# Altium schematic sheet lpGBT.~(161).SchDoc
size C
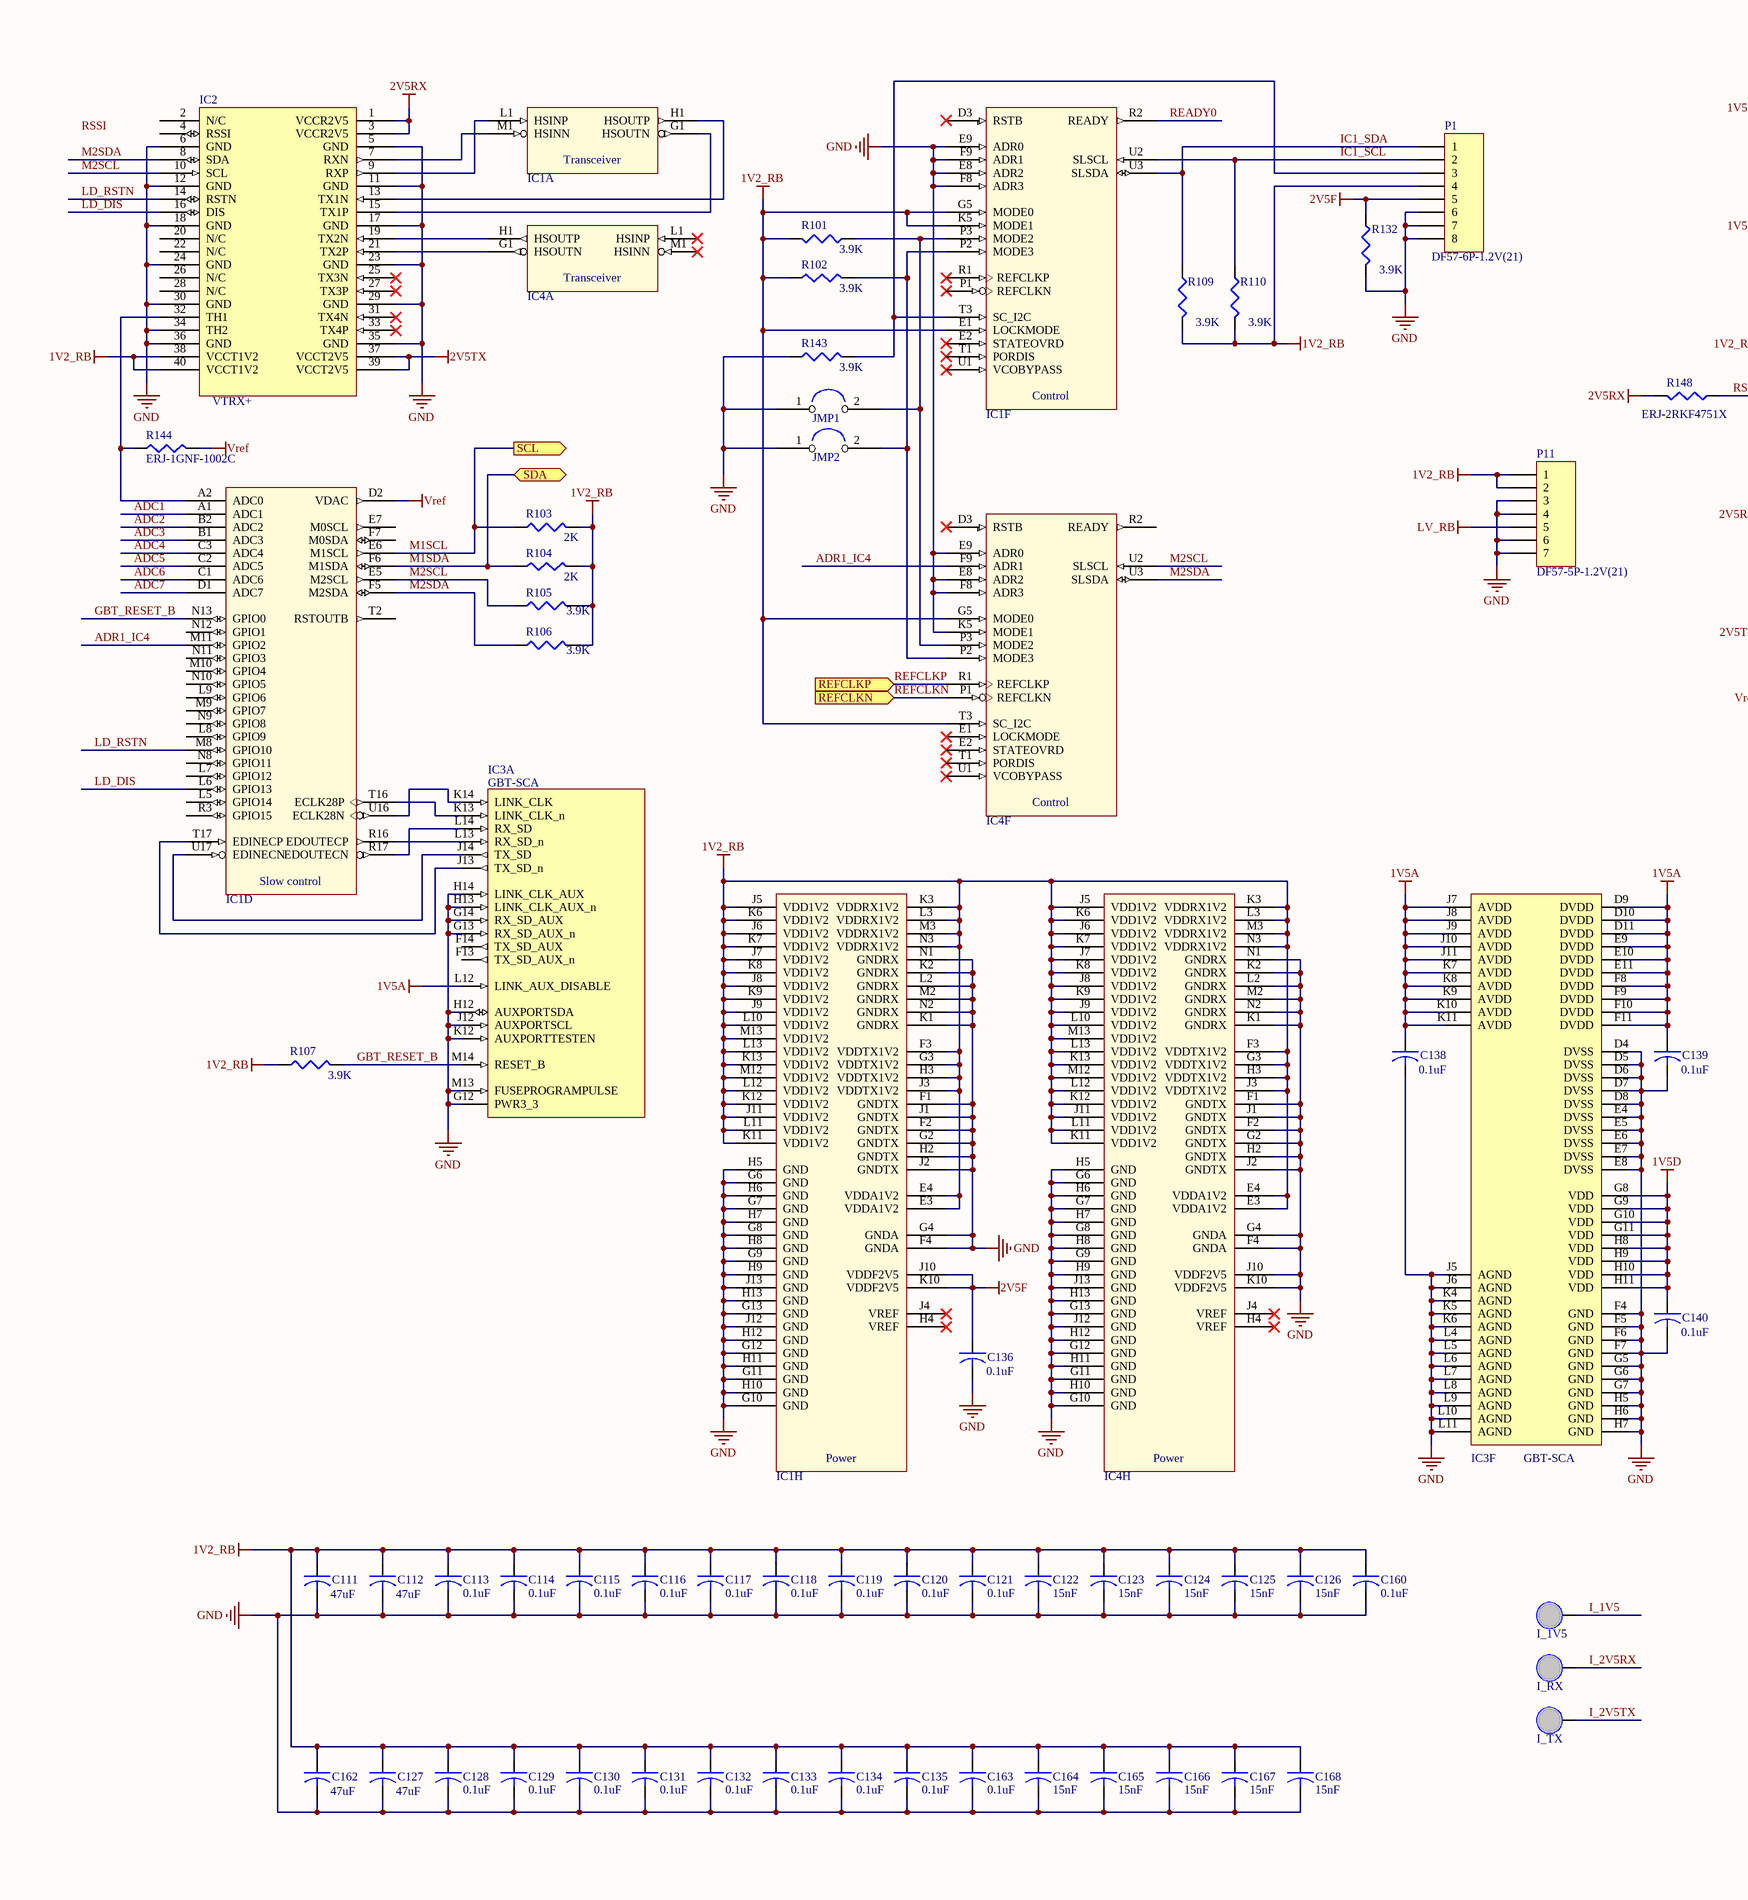
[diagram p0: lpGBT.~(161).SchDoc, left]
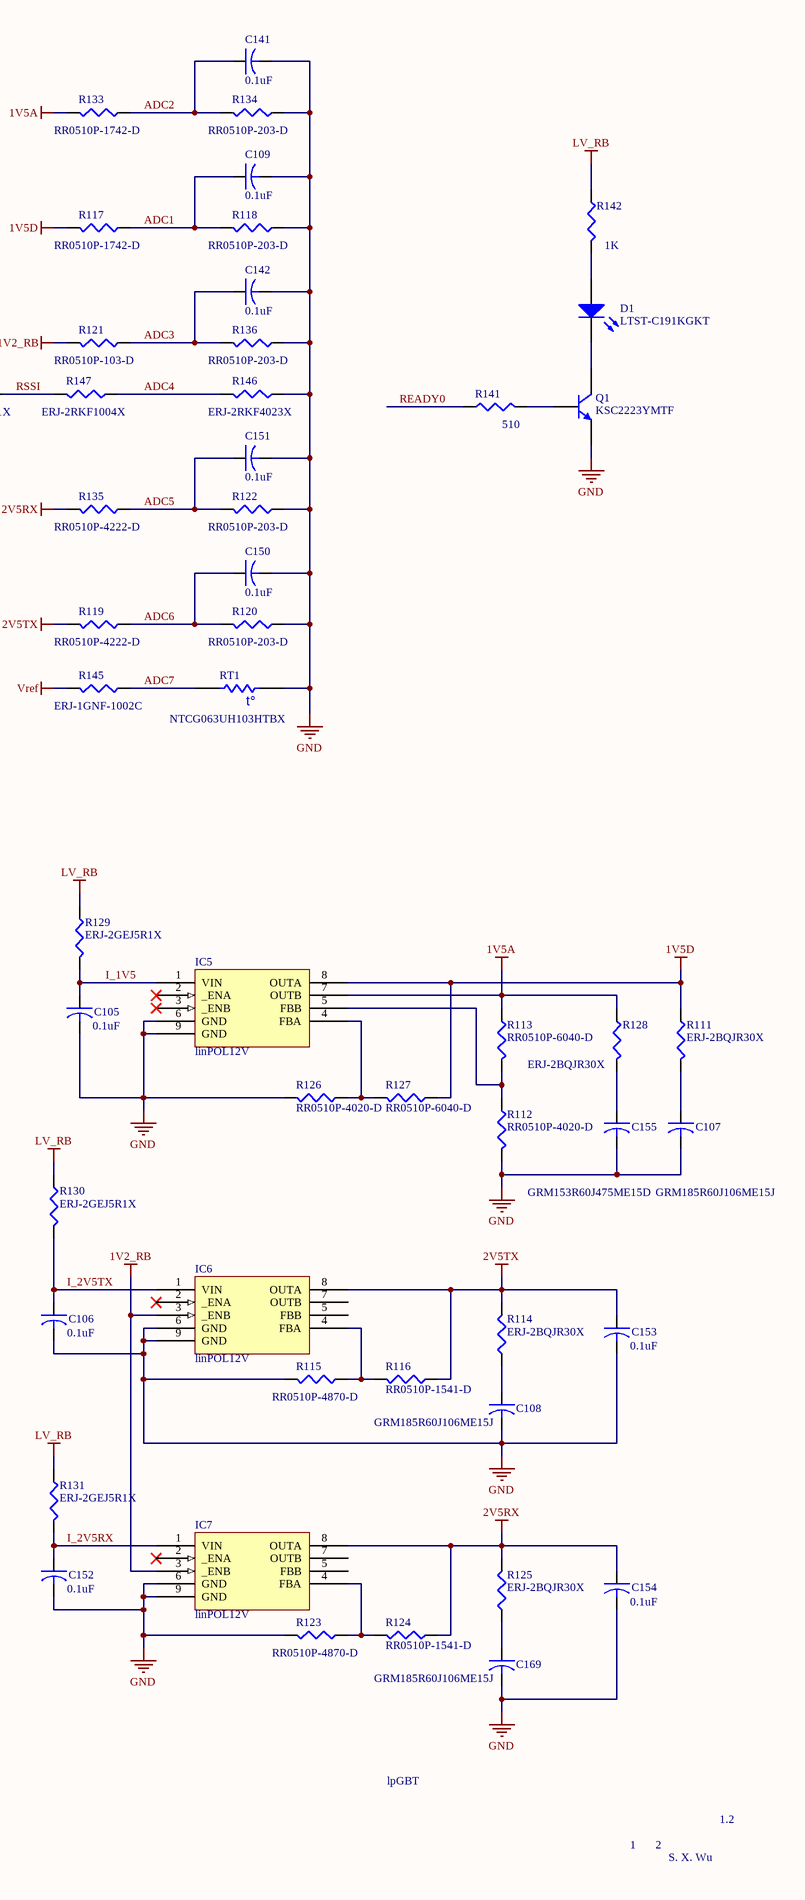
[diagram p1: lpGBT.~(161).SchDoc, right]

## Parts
C105  value 0.1uF  [capc1005n]  (hidden comment: GRM155R71E104ME14D)
C106  value 0.1uF  [capc1005n]  (hidden comment: GRM155R71E104ME14D)
C107  GRM185R60J106ME15J  [CAPC1608N]
C108  GRM185R60J106ME15J  [CAPC1608N]
C109  value 0.1uF  [capc1005n]  (hidden comment: GRM155R71E104ME14D)
C111  value 47uF  [capc2012n]  (hidden comment: GRM188R60J476ME15D)
C112  value 47uF  [capc2012n]  (hidden comment: GRM188R60J476ME15D)
C113  value 0.1uF  [capc0603n]  (hidden comment: GRM033R61C6104KE84D)
C114  value 0.1uF  [capc0603n]  (hidden comment: GRM033R61C6104KE84D)
C115  value 0.1uF  [capc0603n]  (hidden comment: GRM033R61C6104KE84D)
C116  value 0.1uF  [capc0603n]  (hidden comment: GRM033R61C6104KE84D)
C117  value 0.1uF  [capc0603n]  (hidden comment: GRM033R61C6104KE84D)
C118  value 0.1uF  [capc0603n]  (hidden comment: GRM033R61C6104KE84D)
C119  value 0.1uF  [capc0603n]  (hidden comment: GRM033R61C6104KE84D)
C120  value 0.1uF  [capc0603n]  (hidden comment: GRM033R61C6104KE84D)
C121  value 0.1uF  [capc0603n]  (hidden comment: GRM033R61C6104KE84D)
C122  value 15nF  [capc0603n]  (hidden comment: GRM033R61C153KE84D)
C123  value 15nF  [capc0603n]  (hidden comment: GRM033R61C153KE84D)
C124  value 15nF  [capc0603n]  (hidden comment: GRM033R61C153KE84D)
C125  value 15nF  [capc0603n]  (hidden comment: GRM033R61C153KE84D)
C126  value 15nF  [capc0603n]  (hidden comment: GRM033R61C153KE84D)
C127  value 47uF  [capc2012n]  (hidden comment: GRM188R60J476ME15D)
C128  value 0.1uF  [capc0603n]  (hidden comment: GRM033R61C6104KE84D)
C129  value 0.1uF  [capc0603n]  (hidden comment: GRM033R61C6104KE84D)
C130  value 0.1uF  [capc0603n]  (hidden comment: GRM033R61C6104KE84D)
C131  value 0.1uF  [capc0603n]  (hidden comment: GRM033R61C6104KE84D)
C132  value 0.1uF  [capc0603n]  (hidden comment: GRM033R61C6104KE84D)
C133  value 0.1uF  [capc0603n]  (hidden comment: GRM033R61C6104KE84D)
C134  value 0.1uF  [capc0603n]  (hidden comment: GRM033R61C6104KE84D)
C135  value 0.1uF  [capc0603n]  (hidden comment: GRM033R61C6104KE84D)
C136  value 0.1uF  [capc0603n]  (hidden comment: GRM033R61C6104KE84D)
C138  value 0.1uF  [capc1005n]  (hidden comment: GRM155R71E104ME14D)
C139  value 0.1uF  [capc1005n]  (hidden comment: GRM155R71E104ME14D)
C140  value 0.1uF  [capc1005n]  (hidden comment: GRM155R71E104ME14D)
C141  value 0.1uF  [capc1005n]  (hidden comment: GRM155R71E104ME14D)
C142  value 0.1uF  [capc1005n]  (hidden comment: GRM155R71E104ME14D)
C150  value 0.1uF  [capc1005n]  (hidden comment: GRM155R71E104ME14D)
C151  value 0.1uF  [capc1005n]  (hidden comment: GRM155R71E104ME14D)
C152  value 0.1uF  [capc1005n]  (hidden comment: GRM155R71E104ME14D)
C153  value 0.1uF  [capc1005n]  (hidden comment: GRM155R71E104ME14D)
C154  value 0.1uF  [capc1005n]  (hidden comment: GRM155R71E104ME14D)
C155  GRM153R60J475ME15D  [capc1005n]
C160  value 0.1uF  [capc1005n]  (hidden comment: GRM155R71E104ME14D)
C162  value 47uF  [capc2012n]  (hidden comment: GRM188R60J476ME15D)
C163  value 0.1uF  [capc0603n]  (hidden comment: GRM033R61C6104KE84D)
C164  value 15nF  [capc0603n]  (hidden comment: GRM033R61C153KE84D)
C165  value 15nF  [capc0603n]  (hidden comment: GRM033R61C153KE84D)
C166  value 15nF  [capc0603n]  (hidden comment: GRM033R61C153KE84D)
C167  value 15nF  [capc0603n]  (hidden comment: GRM033R61C153KE84D)
C168  value 15nF  [capc0603n]  (hidden comment: GRM033R61C153KE84D)
C169  GRM185R60J106ME15J  [CAPC1608N]
D1  LTST-C191KGKT  [LED_RED]
IC1  LPGBT  [BGA289X17]  (value not drawn)  (parts A,D,F,H of 8)
IC2  DF40C-40DS-0.4V  [vtrx+]  (value not drawn)
IC3  GBT-SCA  [BGA196C80P14X14_1200X1200X170]  (parts A,F of 6)
IC4  LPGBT  [BGA289X17]  (value not drawn)  (parts A,F,H of 8)
IC5  linPOL12V  [WDFNX208]
IC6  linPOL12V  [WDFNX208]
IC7  linPOL12V  [WDFNX208]
JMP1  Not a component, printed on PCB  [JMP2PCB]  (value not drawn)  (no BOM)
JMP2  Not a component, printed on PCB  [JMP2PCB]  (value not drawn)  (no BOM)
P1  DF57-6P-1.2V(21)  [df57-6]
P11  DF57-5P-1.2V(21)  [DF57-5]
Q1  KSC2223YMTF  [SOT-23]
R101  Parameter 1: 3.9K  [resc1005n]  (hidden comment: ERJ-2GEJ392X)
R102  Parameter 1: 3.9K  [resc1005n]  (hidden comment: ERJ-2GEJ392X)
R103  Parameter 1: 2K  [resc1005n]  (hidden comment: ERJ-2GEJ202X)
R104  Parameter 1: 2K  [resc1005n]  (hidden comment: ERJ-2GEJ202X)
R105  Parameter 1: 3.9K  [resc1005n]  (hidden comment: ERJ-2GEJ392X)
R106  Parameter 1: 3.9K  [resc1005n]  (hidden comment: ERJ-2GEJ392X)
R107  Parameter 1: 3.9K  [resc1005n]  (hidden comment: ERJ-2GEJ392X)
R109  Parameter 1: 3.9K  [resc1005n]  (hidden comment: ERJ-2GEJ392X)
R110  Parameter 1: 3.9K  [resc1005n]  (hidden comment: ERJ-2GEJ392X)
R111  ERJ-2BQJR30X  [resc1005n]
R112  RR0510P-4020-D  [resc1005n]
R113  RR0510P-6040-D  [resc1005n]
R114  ERJ-2BQJR30X  [resc1005n]
R115  RR0510P-4870-D  [resc1005n]
R116  RR0510P-1541-D  [resc1005n]
R117  RR0510P-1742-D  [resc1005n]
R118  RR0510P-203-D  [resc1005n]
R119  RR0510P-4222-D  [resc1005n]
R120  RR0510P-203-D  [resc1005n]
R121  RR0510P-103-D  [resc1005n]
R122  RR0510P-203-D  [resc1005n]
R123  RR0510P-4870-D  [resc1005n]
R124  RR0510P-1541-D  [resc1005n]
R125  ERJ-2BQJR30X  [resc1005n]
R126  RR0510P-4020-D  [resc1005n]
R127  RR0510P-6040-D  [resc1005n]
R128  ERJ-2BQJR30X  [resc1005n]
R129  ERJ-2GEJ5R1X  [resc1005n]
R130  ERJ-2GEJ5R1X  [resc1005n]
R131  ERJ-2GEJ5R1X  [resc1005n]
R132  Parameter 1: 3.9K  [resc1005n]  (hidden comment: ERJ-2GEJ392X)
R133  RR0510P-1742-D  [resc1005n]
R134  RR0510P-203-D  [resc1005n]
R135  RR0510P-4222-D  [resc1005n]
R136  RR0510P-203-D  [resc1005n]
R141  Parameter 1: 510  [resc1005n]  (hidden comment: ERJ-2GEJ511X)
R142  Parameter 1: 1K  [resc1005n]  (hidden comment: ERJ-2GEJ102X)
R143  Parameter 1: 3.9K  [resc1005n]  (hidden comment: ERJ-2GEJ392X)
R144  ERJ-1GNF-1002C  [resc0603]
R145  ERJ-1GNF-1002C  [resc0603]
R146  ERJ-2RKF4023X  [resc1005n]
R147  ERJ-2RKF1004X  [resc1005n]
R148  ERJ-2RKF4751X  [resc1005n]
RT1  NTCG063UH103HTBX  [resc0603]
TP15  I_1V5  [testpoint]  (no BOM)
TP16  I_RX  [testpoint]  (no BOM)
TP17  I_TX  [testpoint]  (no BOM)

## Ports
REFCLKN (in), REFCLKP (in), SCL (out), SDA (bidir)

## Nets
1V2_RB: C111.1 C112.1 C113.1 C114.1 C115.1 C116.1 C117.1 C118.1 C119.1 C120.1 C121.1 C122.1 C123.1 C124.1 C125.1 C126.1 C127.1 C128.1 C129.1 C130.1 C131.1 C132.1 C133.1 C134.1 C135.1 C160.1 C162.1 C163.1 C164.1 C165.1 C166.1 C167.1 C168.1 IC1.E1(LOCKMODE) IC1.E3(VDDA1V2) IC1.E4(VDDA1V2) IC1.F3(VDDTX1V2) IC1.G3(VDDTX1V2) IC1.G5(MODE0) IC1.H3(VDDTX1V2) IC1.J3(VDDTX1V2) IC1.J5(VDD1V2) IC1.J6(VDD1V2) IC1.J7(VDD1V2) IC1.J8(VDD1V2) IC1.J9(VDD1V2) IC1.J11(VDD1V2) IC1.K3(VDDRX1V2) IC1.K5(MODE1) IC1.K6(VDD1V2) IC1.K7(VDD1V2) IC1.K8(VDD1V2) IC1.K9(VDD1V2) IC1.K11(VDD1V2) IC1.K12(VDD1V2) IC1.K13(VDD1V2) IC1.L3(VDDRX1V2) IC1.L10(VDD1V2) IC1.L11(VDD1V2) IC1.L12(VDD1V2) IC1.L13(VDD1V2) IC1.M3(VDDRX1V2) IC1.M12(VDD1V2) IC1.M13(VDD1V2) IC1.N3(VDDRX1V2) IC2.38(VCCT1V2) IC2.40(VCCT1V2) IC4.E3(VDDA1V2) IC4.E4(VDDA1V2) IC4.F3(VDDTX1V2) IC4.G3(VDDTX1V2) IC4.G5(MODE0) IC4.H3(VDDTX1V2) IC4.J3(VDDTX1V2) IC4.J5(VDD1V2) IC4.J6(VDD1V2) IC4.J7(VDD1V2) IC4.J8(VDD1V2) IC4.J9(VDD1V2) IC4.J11(VDD1V2) IC4.K3(VDDRX1V2) IC4.K6(VDD1V2) IC4.K7(VDD1V2) IC4.K8(VDD1V2) IC4.K9(VDD1V2) IC4.K11(VDD1V2) IC4.K12(VDD1V2) IC4.K13(VDD1V2) IC4.L3(VDDRX1V2) IC4.L10(VDD1V2) IC4.L11(VDD1V2) IC4.L12(VDD1V2) IC4.L13(VDD1V2) IC4.M3(VDDRX1V2) IC4.M12(VDD1V2) IC4.M13(VDD1V2) IC4.N3(VDDRX1V2) IC4.T3(SC_I2C) IC6.3(_ENB) IC7.3(_ENB) P1.4 P11.1 P11.2 R101.2 R102.1 R103.2 R104.2 R105.2 R106.2 R107.1 R109.2 R110.2 R121.2
1V5A: C138.1 C139.1 IC3.D9(DVDD) IC3.D10(DVDD) IC3.D11(DVDD) IC3.E9(DVDD) IC3.E10(DVDD) IC3.E11(DVDD) IC3.F8(DVDD) IC3.F9(DVDD) IC3.F10(DVDD) IC3.F11(DVDD) IC3.J7(AVDD) IC3.J8(AVDD) IC3.J9(AVDD) IC3.J10(AVDD) IC3.J11(AVDD) IC3.K7(AVDD) IC3.K8(AVDD) IC3.K9(AVDD) IC3.K10(AVDD) IC3.K11(AVDD) IC3.L12(LINK_AUX_DISABLE) IC5.7(OUTB) R113.1 R128.1 R133.2
1V5D: C140.1 IC3.G8(VDD) IC3.G9(VDD) IC3.G10(VDD) IC3.G11(VDD) IC3.H8(VDD) IC3.H9(VDD) IC3.H10(VDD) IC3.H11(VDD) IC5.8(OUTA) R111.1 R117.2 R127.1
2V5F: C136.1 IC1.J10(VDDF2V5) IC1.K10(VDDF2V5) P1.5 R132.1
2V5RX: C154.1 IC2.1(VCCR2V5) IC2.3(VCCR2V5) IC7.8(OUTA) R124.1 R125.2 R135.2 R148.2
2V5TX: C153.1 IC2.37(VCCT2V5) IC2.39(VCCT2V5) IC6.8(OUTA) R114.2 R116.1 R119.2
GND: C105.2 C106.2 C107.2 C108.2 C109.2 C111.2 C112.2 C113.2 C114.2 C115.2 C116.2 C117.2 C118.2 C119.2 C120.2 C121.2 C122.2 C123.2 C124.2 C125.2 C126.2 C127.2 C128.2 C129.2 C130.2 C131.2 C132.2 C133.2 C134.2 C135.2 C136.2 C138.2 C139.2 C140.2 C141.2 C142.2 C150.2 C151.2 C152.2 C153.2 C154.2 C155.2 C160.2 C162.2 C163.2 C164.2 C165.2 C166.2 C167.2 C168.2 C169.2 IC1.E8(ADR2) IC1.E9(ADR0) IC1.F1(GNDTX) IC1.F2(GNDTX) IC1.F4(GNDA) IC1.F8(ADR3) IC1.F9(ADR1) IC1.G2(GNDTX) IC1.G4(GNDA) IC1.G6(GND) IC1.G7(GND) IC1.G8(GND) IC1.G9(GND) IC1.G10(GND) IC1.G11(GND) IC1.G12(GND) IC1.G13(GND) IC1.H2(GNDTX) IC1.H5(GND) IC1.H6(GND) IC1.H7(GND) IC1.H8(GND) IC1.H9(GND) IC1.H10(GND) IC1.H11(GND) IC1.H12(GND) IC1.H13(GND) IC1.J1(GNDTX) IC1.J2(GNDTX) IC1.J12(GND) IC1.J13(GND) IC1.K1(GNDRX) IC1.K2(GNDRX) IC1.L2(GNDRX) IC1.M2(GNDRX) IC1.N1(GNDRX) IC1.N2(GNDRX) IC2.5(GND) IC2.6(GND) IC2.11(GND) IC2.12(GND) IC2.17(GND) IC2.18(GND) IC2.23(GND) IC2.24(GND) IC2.29(GND) IC2.30(GND) IC2.34(TH2) IC2.35(GND) IC2.36(GND) IC3.D4(DVSS) IC3.D5(DVSS) IC3.D6(DVSS) IC3.D7(DVSS) IC3.D8(DVSS) IC3.E4(DVSS) IC3.E5(DVSS) IC3.E6(DVSS) IC3.E7(DVSS) IC3.E8(DVSS) IC3.F4(GND) IC3.F5(GND) IC3.F6(GND) IC3.F7(GND) IC3.G5(GND) IC3.G6(GND) IC3.G7(GND) IC3.G12(PWR3_3) IC3.G13(RX_SD_AUX_n) IC3.G14(RX_SD_AUX) IC3.H5(GND) IC3.H6(GND) IC3.H7(GND) IC3.H12(AUXPORTSDA) IC3.H13(LINK_CLK_AUX_n) IC3.H14(LINK_CLK_AUX) IC3.J5(AGND) IC3.J6(AGND) IC3.J12(AUXPORTSCL) IC3.K4(AGND) IC3.K5(AGND) IC3.K6(AGND) IC3.K12(AUXPORTTESTEN) IC3.L4(AGND) IC3.L5(AGND) IC3.L6(AGND) IC3.L7(AGND) IC3.L8(AGND) IC3.L9(AGND) IC3.L10(AGND) IC3.L11(AGND) IC3.M13(FUSEPROGRAMPULSE) IC4.E8(ADR2) IC4.E9(ADR0) IC4.F1(GNDTX) IC4.F2(GNDTX) IC4.F4(GNDA) IC4.F8(ADR3) IC4.G2(GNDTX) IC4.G4(GNDA) IC4.G6(GND) IC4.G7(GND) IC4.G8(GND) IC4.G9(GND) IC4.G10(GND) IC4.G11(GND) IC4.G12(GND) IC4.G13(GND) IC4.H2(GNDTX) IC4.H5(GND) IC4.H6(GND) IC4.H7(GND) IC4.H8(GND) IC4.H9(GND) IC4.H10(GND) IC4.H11(GND) IC4.H12(GND) IC4.H13(GND) IC4.J1(GNDTX) IC4.J2(GNDTX) IC4.J10(VDDF2V5) IC4.J12(GND) IC4.J13(GND) IC4.K1(GNDRX) IC4.K2(GNDRX) IC4.K5(MODE1) IC4.K10(VDDF2V5) IC4.L2(GNDRX) IC4.M2(GNDRX) IC4.N1(GNDRX) IC4.N2(GNDRX) IC5.6(GND) IC5.9(GND) IC6.6(GND) IC6.9(GND) IC7.6(GND) IC7.9(GND) JMP1.1 JMP2.1 P1.6 P1.7 P1.8 P11.3 P11.4 P11.6 P11.7 Q1.3(E) R112.2 R115.2 R118.1 R120.1 R122.1 R123.2 R126.2 R132.2 R134.1 R136.1 R143.1 R146.1 RT1.1
LV_RB: P11.5 R129.1 R130.1 R131.1 R142.1
Vref: IC1.D2(VDAC) R144.2 R145.2
ADC1: C109.1 IC1.A1(ADC1) R117.1 R118.2
ADC2: C141.1 IC1.B2(ADC2) R133.1 R134.2
ADC3: C142.1 IC1.B1(ADC3) R121.1 R136.2
ADC4: IC1.C3(ADC4) R146.2 R147.1
ADC5: C151.1 IC1.C2(ADC5) R122.2 R135.1
ADC6: C150.1 IC1.C1(ADC6) R119.1 R120.2
ADC7: IC1.D1(ADC7) R145.1 RT1.2
ADR1_IC4: IC1.M11(GPIO2) IC4.F9(ADR1)
GBT_RESET_B: IC1.N13(GPIO0) IC3.M14(RESET_B) R107.2
I_1V5: C105.1 IC5.1(VIN) R129.2 TP15.1(TP)
I_2V5RX: C152.1 IC7.1(VIN) R131.2 TP16.1(TP)
I_2V5TX: C106.1 IC6.1(VIN) R130.2 TP17.1(TP)
IC1_SCL: IC1.U2(SLSCL) P1.2 R110.1
IC1_SDA: IC1.U3(SLSDA) P1.1 R109.1
LD_DIS: IC1.L6(GPIO13) IC2.16(DIS)
LD_RSTN: IC1.M8(GPIO10) IC2.14(RSTN)
M1SCL: IC1.E6(M1SCL) R103.1 ; port SCL
M1SDA: IC1.F6(M1SDA) R104.1 ; port SDA
M2SCL: IC1.E5(M2SCL) IC2.10(SCL) IC4.U2(SLSCL) R105.1
M2SDA: IC1.F5(M2SDA) IC2.8(SDA) IC4.U3(SLSDA) R106.1
READY0: IC1.R2(READY) R141.1
REFCLKN: IC4.P1(REFCLKN) ; port REFCLKN
REFCLKP: IC4.R1(REFCLKP) ; port REFCLKP
RSSI: R147.2 R148.1
NetC107_1: C107.1 R111.2
NetC108_1: C108.1 R114.1
NetC155_1: C155.1 R128.2
NetC169_1: C169.1 R125.1
NetD1_1: D1.1(A) R142.2
NetD1_2: D1.2(K) Q1.1(C)
NetIC1_A2: IC1.A2(ADC0) IC2.32(TH1) R144.1
NetIC1_G1: IC1.G1(HSOUTN) IC2.15(TX1P)
NetIC1_H1: IC1.H1(HSOUTP) IC2.13(TX1N)
NetIC1_L1: IC1.L1(HSINP) IC2.9(RXP)
NetIC1_M1: IC1.M1(HSINN) IC2.7(RXN)
NetIC1_P2: IC1.P2(MODE3) IC4.P2(MODE3) JMP2.2 R102.2
NetIC1_P3: IC1.P3(MODE2) IC4.P3(MODE2) JMP1.2 R101.1
NetIC1_R16: IC1.R16(EDOUTECP) IC3.L13(RX_SD_n)
NetIC1_R17: IC1.R17(EDOUTECN) IC3.L14(RX_SD)
NetIC1_T3: IC1.T3(SC_I2C) P1.3 R143.2
NetIC1_T16: IC1.T16(ECLK28P) IC3.K13(LINK_CLK_n)
NetIC1_T17: IC1.T17(EDINECP) IC3.J13(TX_SD_n)
NetIC1_U16: IC1.U16(ECLK28N) IC3.K14(LINK_CLK)
NetIC1_U17: IC1.U17(EDINECN) IC3.J14(TX_SD)
NetIC2_19: IC2.19(TX2N) IC4.H1(HSOUTP)
NetIC2_21: IC2.21(TX2P) IC4.G1(HSOUTN)
NetIC5_4: IC5.4(FBA) R126.1 R127.2
NetIC5_5: IC5.5(FBB) R112.1 R113.2
NetIC6_4: IC6.4(FBA) R115.1 R116.2
NetIC7_4: IC7.4(FBA) R123.1 R124.2
NetQ1_2: Q1.2(B) R141.2

Not connected (* = marked no-connect by the designer): IC1 D3(RSTB)* E2(STATEOVRD)* E7(M0SCL) F7(M0SDA) H4(VREF)* J4(VREF)* L5(GPIO14) L7(GPIO12) L8(GPIO9) L9(GPIO6) M9(GPIO7) M10(GPIO4) N8(GPIO11) N9(GPIO8) N10(GPIO5) N11(GPIO3) N12(GPIO1) P1(REFCLKN)* R1(REFCLKP)* R3(GPIO15) T1(PORDIS)* T2(RSTOUTB) U1(VCOBYPASS)*; IC2 2(N/C) 4(RSSI) 20(N/C) 22(N/C) 25(TX3N)* 26(N/C) 27(TX3P)* 28(N/C) 31(TX4N)* 33(TX4P)*; IC3 F13(TX_SD_AUX_n) F14(TX_SD_AUX); IC4 D3(RSTB)* E1(LOCKMODE)* E2(STATEOVRD)* H4(VREF)* J4(VREF)* L1(HSINP)* M1(HSINN)* R2(READY) T1(PORDIS)* U1(VCOBYPASS)*; IC5 2(_ENA)* 3(_ENB)*; IC6 2(_ENA)* 5(FBB) 7(OUTB); IC7 2(_ENA)* 5(FBB) 7(OUTB)

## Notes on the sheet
- lpGBT
- 1
- 2
- S. X. Wu
- 1.2
- Labels drawn without touching a wire or pin: RSSI

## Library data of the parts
C105 C106 C109 C111-C136 C138-C142 C150-C154 C160 C162-C168 = C: CERAMIC CAPACITOR
C107 C108 C169 = C: CERAMIC CAPACITOR; VALUE: 10uF
C155 = C: CERAMIC CAPACITOR; VALUE: 4.7uF
D1 = LED2: Typical RED, GREEN, YELLOW, AMBER GaAs LED
IC1 IC4 = LPGBT: Low Power Gigabit Transceiver; Manufacturer: CERN; Pinout Version: 180226; Bonding: No
IC2 = VTRX+_DF40C-2.0-40DS-0.4V: VTRX+ module with 2.5mm stack Height.
IC3 = CERN_GBT-SCA_REV 6.2: The Slow Control Adapter ASIC for the GBT System
JMP1 JMP2 = JMP2: printed on PCB
P1 = Header 8: Header, 8-Pin
P11 = Header 7: Header, 7-Pin
Q1 = NPN: NPN Bipolar Transistor
R101-R104 R107 R109 R110 R132 R141-R143 = R1: FILM RESISTOR; Text Field2: 5%
R105 R106 R111-R131 R133-R136 R144 R145 = R1: FILM RESISTOR; Text Field2: 1%
R146 = R1: FILM RESISTOR; Text Field2: 1%; Parameter 1: 402K
R147 = R1: FILM RESISTOR; Text Field2: 1%; Parameter 1: 1M
R148 = R1: FILM RESISTOR; Text Field2: 1%; Parameter 1: 4.75K
RT1 = Res Thermal: Thermistor
TP15-TP17 = TP: TEST POINT 40MIL DIA.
